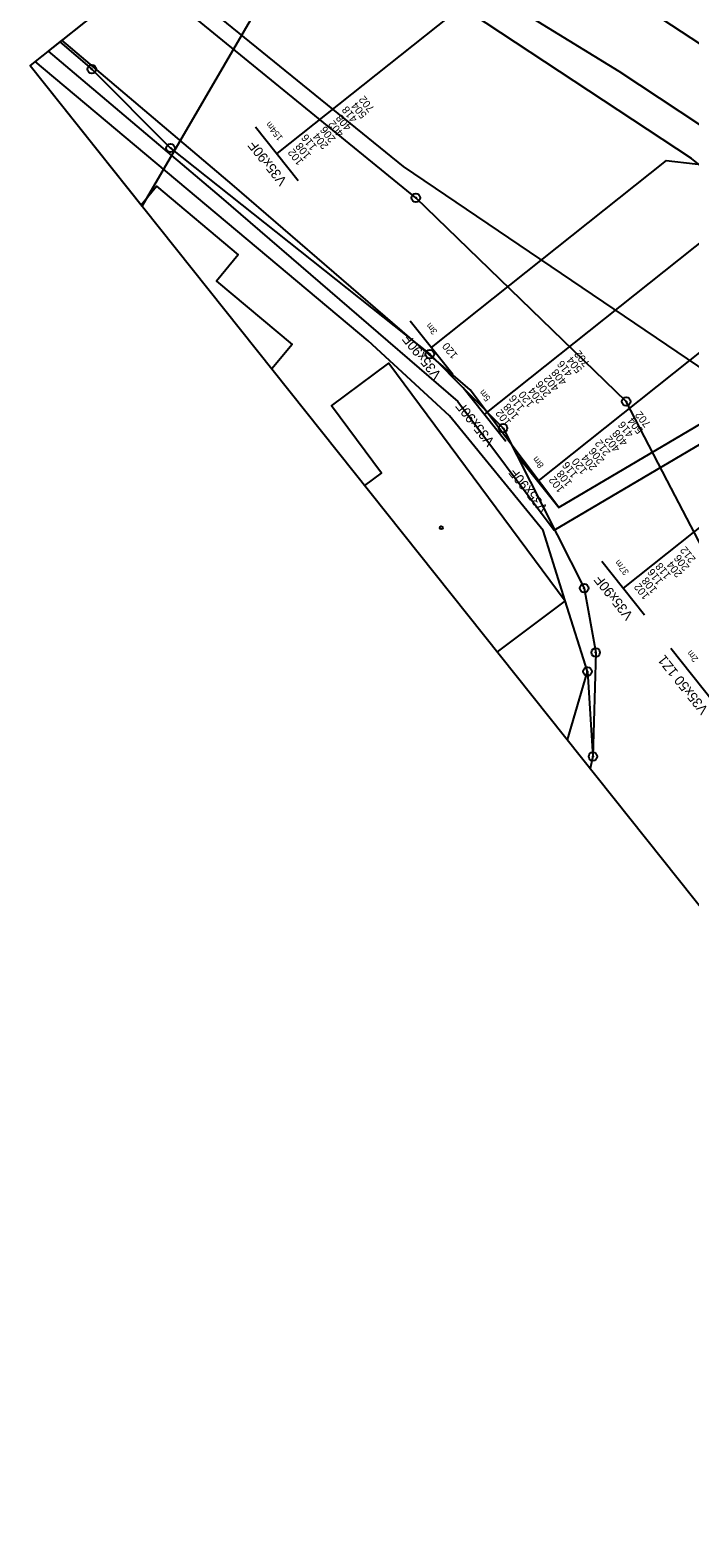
# Model space of a CAD drawing. Extents: x -620412 to -620034, y -1122986 to -1122565.
# Drawn here: x -620412.1 to -620334.9, y -1122830 to -1122653.6 of the extents above; entities that cross this region are included whole.
import ezdxf

# ---------------------------------------------------------------- set-up
doc = ezdxf.new("R2010")
doc.units = 0
for name, color, linetype in [('HranDP', 7, 'Continuous'), ('Hranice parcel', 7, 'Continuous'), ('Rámečky-tisk', 7, 'Continuous'), ('Vrstva 1', 7, 'Continuous'), ('Vrstva 14', 7, 'Continuous'), ('Vrstva 33', 7, 'Continuous'), ('Věcná břemena k části', 7, 'Continuous'), ('Značky bodu BP', 7, 'Continuous'), ('Značky budov', 7, 'Continuous')]:
    doc.layers.add(name, color=color, linetype=linetype)

msp = doc.modelspace()

# ---------------------------------------------------------------- linework, layer by layer
at = {"layer": 'HranDP'}
msp.add_lwpolyline([(-620310.57, -1122708.76), (-620306.2, -1122698.65), (-620309.9, -1122688.62), (-620334.71, -1122668.63), (-620384.5, -1122635.77)], dxfattribs=at)
at = {"layer": 'Hranice parcel'}
for p, q in [((-620349.25, -1122736.67), (-620346.9, -1122728.66)), ((-620346.9, -1122728.66), (-620346.26, -1122738.61))]:
    msp.add_line(p, q, dxfattribs=at)
for points in [[(-620310.57, -1122708.76), (-620306.2, -1122698.65), (-620309.9, -1122688.62), (-620334.71, -1122668.63), (-620384.5, -1122635.77)], [(-620342.37, -1122697.07), (-620366.98, -1122673.23), (-620398.86, -1122647.21)], [(-620397.41, -1122646.05), (-620368.46, -1122669.58), (-620310.57, -1122708.76)], [(-620408.64, -1122654.99), (-620404.9, -1122658.18), (-620395.68, -1122667.41), (-620365.35, -1122691.52), (-620356.78, -1122700.2), (-620347.29, -1122718.92), (-620345.94, -1122726.44), (-620346.26, -1122738.61)], [(-620346.9, -1122728.66), (-620349.5, -1122720.4), (-620352.08, -1122712.18), (-620363.06, -1122698.75), (-620372.55, -1122689.97), (-620411.52, -1122657.29)], [(-620399.14, -1122674.04), (-620397.34, -1122671.88), (-620387.77, -1122679.92), (-620390.32, -1122682.97), (-620381.44, -1122690.4), (-620383.84, -1122693.25)], [(-620372.96, -1122706.91), (-620370.99, -1122705.44), (-620376.85, -1122697.59), (-620370.13, -1122692.59), (-620349.5, -1122720.4)], [(-620328.93, -1122734.05), (-620330.51, -1122726.08), (-620332.51, -1122716.01), (-620337.56, -1122706.31), (-620342.37, -1122697.07)], [(-620349.5, -1122720.4), (-620357.46, -1122726.36)], [(-620346.26, -1122738.61), (-620346.59, -1122740.01)]]:
    msp.add_lwpolyline(points, dxfattribs=at)
at = {"layer": 'Rámečky-tisk'}
for p, q in [((-620295.96, -1122565.23), (-620412.11, -1122657.76)), ((-620399.01, -1122674.21), (-620369.88, -1122624.12))]:
    msp.add_line(p, q, dxfattribs=at)
for points in [[(-620412.11, -1122657.76), (-620150.41, -1122986.26), (-620034.26, -1122893.74), (-620295.96, -1122565.23)], [(-620369.88, -1122624.12), (-620412.11, -1122657.76), (-620399.01, -1122674.21)]]:
    msp.add_lwpolyline(points, dxfattribs=at)
at = {"layer": 'Vrstva 1'}
msp.add_lwpolyline([(-620326.63, -1122669.41), (-620343.18, -1122658.46), (-620368.5, -1122642.9), (-620382.24, -1122633.97)], dxfattribs=at)
at = {"layer": 'Vrstva 14'}
msp.add_lwpolyline([(-620375.56, -1122628.64), (-620368.73, -1122632.95), (-620361.89, -1122637.25), (-620355.04, -1122641.55), (-620347.33, -1122646.47), (-620340.48, -1122650.8), (-620333.68, -1122655.25), (-620327.8, -1122659.17), (-620324.47, -1122661.49), (-620319.64, -1122664.92)], dxfattribs=at)
at = {"layer": 'Vrstva 33'}
for p, q in [((-620358.99, -1122648.74), (-620383.24, -1122668.06)), ((-620385.73, -1122664.93), (-620380.74, -1122671.19)), ((-620337.71, -1122668.87), (-620365.17, -1122690.74)), ((-620337.71, -1122668.87), (-620327.09, -1122670.07)), ((-620324.29, -1122670.96), (-620358.93, -1122698.56)), ((-620320.83, -1122680.99), (-620352.7, -1122706.39)), ((-620302.02, -1122686.47), (-620342.73, -1122718.9)), ((-620367.66, -1122687.61), (-620362.67, -1122693.87)), ((-620361.43, -1122695.43), (-620356.44, -1122701.69)), ((-620355.2, -1122703.26), (-620350.21, -1122709.51)), ((-620345.23, -1122715.77), (-620340.24, -1122722.03)), ((-620337.13, -1122725.94), (-620332.14, -1122732.2))]:
    msp.add_line(p, q, dxfattribs=at)
at = {"layer": 'Věcná břemena k části'}
msp.add_line((-620408.4, -1122654.8), (-620409.99, -1122656.07), dxfattribs=at)
msp.add_lwpolyline([(-620409.99, -1122656.07), (-620389.78, -1122673.21), (-620362.07, -1122697.07), (-620350.79, -1122712.11), (-620329.91, -1122699.79), (-620318.75, -1122707.75), (-620310.23, -1122716.49), (-620285.9, -1122736.09), (-620287.87, -1122738.92), (-620280.66, -1122744.45), (-620246.32, -1122763.41), (-620202.66, -1122784.39), (-620201.79, -1122782.59), (-620245.45, -1122761.61), (-620279.7, -1122742.7), (-620285.15, -1122738.52), (-620283.23, -1122735.73), (-620308.89, -1122715.01), (-620317.45, -1122706.23), (-620329.81, -1122697.41), (-620350.27, -1122709.47), (-620360.61, -1122695.69), (-620388.48, -1122671.69), (-620408.4, -1122654.8)], dxfattribs=at)
at = {"layer": 'Značky bodu BP'}
for centre, radius in [((-620404.9, -1122658.18), 0.5), ((-620404.9, -1122658.18), 0.0303), ((-620395.68, -1122667.41), 0.5), ((-620395.68, -1122667.41), 0.0303), ((-620366.98, -1122673.23), 0.5), ((-620366.98, -1122673.23), 0.0303), ((-620365.35, -1122691.52), 0.5), ((-620365.35, -1122691.52), 0.0303), ((-620342.37, -1122697.07), 0.5), ((-620342.37, -1122697.07), 0.0303), ((-620356.78, -1122700.2), 0.5), ((-620356.78, -1122700.2), 0.0303), ((-620347.29, -1122718.92), 0.5), ((-620347.29, -1122718.92), 0.0303), ((-620345.94, -1122726.44), 0.5), ((-620345.94, -1122726.44), 0.0303), ((-620346.9, -1122728.66), 0.5), ((-620346.9, -1122728.66), 0.0303), ((-620346.26, -1122738.61), 0.5), ((-620346.26, -1122738.61), 0.0303)]:
    msp.add_circle(centre, radius, dxfattribs=at)
at = {"layer": 'Značky budov'}
msp.add_circle((-620364, -1122711.85), 0.175, dxfattribs=at)

# ---------------------------------------------------------------- texts
at = {"layer": 'Vrstva 33'}
for s, height, p in [('702', 0.9, (-620371.78, -1122662.77)), ('408', 0.9, (-620374.46, -1122664.95)), ('418', 0.9, (-620373.76, -1122663.98)), ('504', 0.9, (-620372.66, -1122663.51)), ('154m', 0.75, (-620382.49, -1122666.19)), ('206', 0.9, (-620376.31, -1122666.33)), ('402', 0.9, (-620375.36, -1122665.66)), ('V35x90F', 1.15, (-620381.99, -1122671.23)), ('108', 0.9, (-620379.19, -1122668.25)), ('116', 0.9, (-620378.51, -1122667.25)), ('204', 0.9, (-620377.16, -1122667.1)), ('102', 0.9, (-620380.08, -1122668.97)), ('3m', 0.75, (-620364.42, -1122688.87)), ('V35x90F', 1.15, (-620363.92, -1122693.91)), ('120', 0.9, (-620362.02, -1122691.65)), ('504', 0.9, (-620347.46, -1122693.3)), ('702', 0.9, (-620346.58, -1122692.56)), ('408', 0.9, (-620349.26, -1122694.73)), ('416', 0.9, (-620348.58, -1122693.74)), ('206', 0.9, (-620351.11, -1122696.11)), ('402', 0.9, (-620350.16, -1122695.45)), ('5m', 0.75, (-620358.19, -1122696.69)), ('116', 0.9, (-620354.21, -1122697.76)), ('120', 0.9, (-620353.09, -1122697.31)), ('204', 0.9, (-620351.96, -1122696.88)), ('V35x90F', 1.15, (-620357.69, -1122701.73)), ('102', 0.9, (-620355.78, -1122699.47)), ('108', 0.9, (-620354.88, -1122698.75)), ('702', 0.9, (-620339.45, -1122699.67)), ('408', 0.9, (-620342.13, -1122701.84)), ('416', 0.9, (-620341.45, -1122700.85)), ('504', 0.9, (-620340.33, -1122700.41)), ('212', 0.9, (-620344.15, -1122703)), ('402', 0.9, (-620343.03, -1122702.56)), ('8m', 0.75, (-620351.96, -1122704.51)), ('116', 0.9, (-620347.98, -1122705.58)), ('120', 0.9, (-620346.86, -1122705.14)), ('204', 0.9, (-620345.73, -1122704.71)), ('206', 0.9, (-620344.88, -1122703.93)), ('V35x90F', 1.15, (-620351.46, -1122709.55)), ('102', 0.9, (-620349.55, -1122707.29)), ('108', 0.9, (-620348.65, -1122706.57)), ('212', 0.9, (-620334.18, -1122715.51)), ('37m', 0.75, (-620341.99, -1122717.03)), ('118', 0.9, (-620337.08, -1122717.41)), ('204', 0.9, (-620335.76, -1122717.22)), ('206', 0.9, (-620334.91, -1122716.45)), ('V35x90F', 1.15, (-620341.49, -1122722.07)), ('102', 0.9, (-620339.58, -1122719.8)), ('108', 0.9, (-620338.68, -1122719.09)), ('116', 0.9, (-620338.01, -1122718.09)), ('V35x50 1Z1', 1.15, (-620332.7, -1122733.11)), ('2m', 0.75, (-620333.89, -1122727.19))]:
    msp.add_text(s, height=height, rotation=128.542, dxfattribs=at).set_placement(p)

doc.saveas('drawing.dxf')
